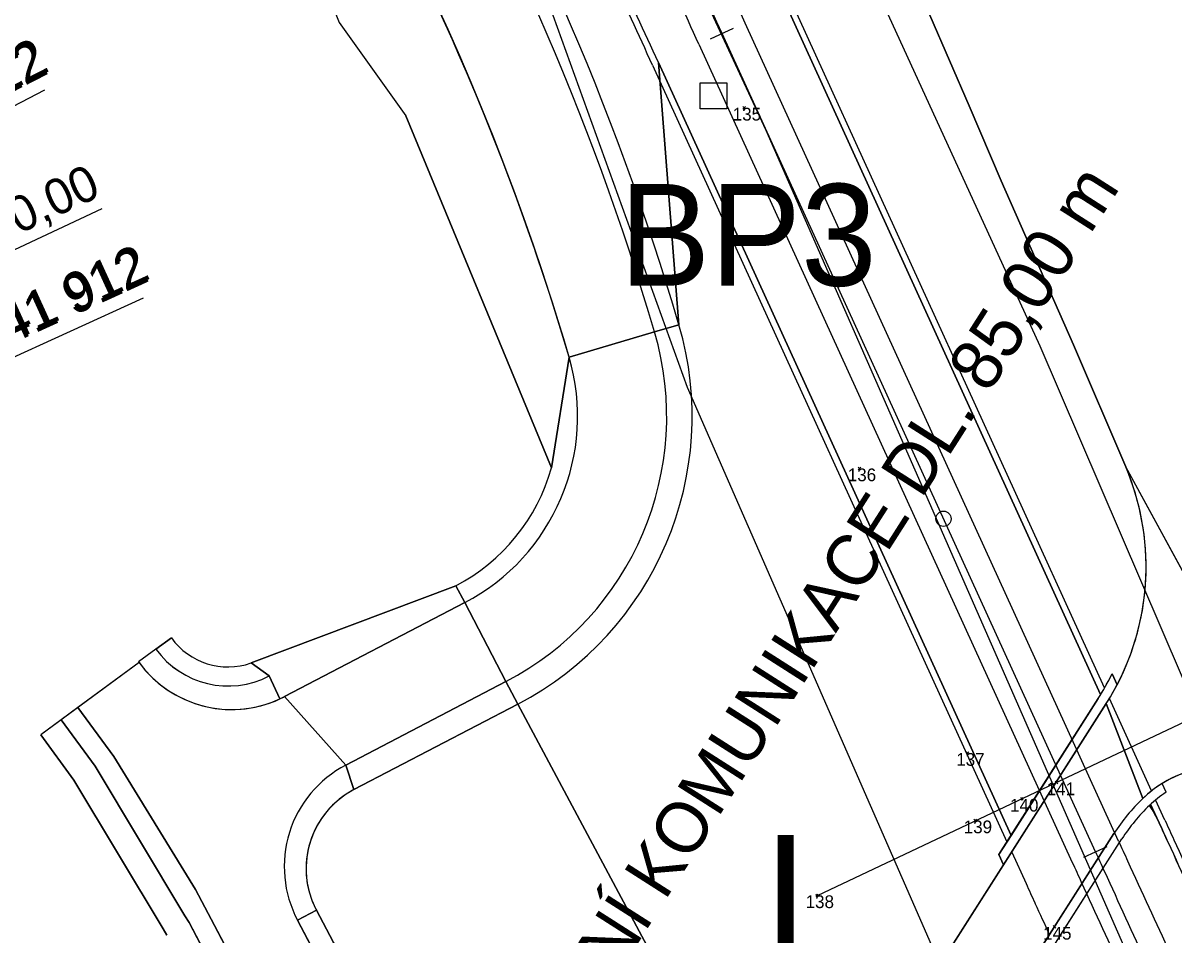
# Model space of a CAD drawing. Extents: x -606444 to -604546, y -1158114 to -1156869.
# Drawn here: x -605195.8 to -605105.4, y -1157332.6 to -1157260.9 of the extents above; entities that cross this region are included whole.
import ezdxf

# ---------------------------------------------------------------- set-up
doc = ezdxf.new("R2010")
doc.units = 0
for name, color, linetype in [('B_CHOD', 7, 'Continuous'), ('B_TRAM', 7, 'Continuous'), ('B_VOZ', 7, 'Continuous'), ('B_ZELEN', 7, 'Continuous'), ('geofyzikální profily_předběžný GTP', 7, 'Continuous'), ('korozní průzkum', 7, 'Continuous'), ('NS_VB', 7, 'Continuous'), ('NS_VB_OBJ', 7, 'Continuous'), ('NS_VB_POP', 7, 'Continuous'), ('OSA', 7, 'Continuous'), ('OSAPOP', 7, 'Continuous'), ('podélný profil trasou tramvaje', 7, 'Continuous'), ('stabilitní profily_předběžný GTP', 7, 'Continuous')]:
    doc.layers.add(name, color=color, linetype=linetype)

msp = doc.modelspace()

# ---------------------------------------------------------------- linework, layer by layer
for p, q in [((-605139.16, -1157267.56), (-605139.26, -1157267.46)), ((-605139.16, -1157267.56), (-605139.26, -1157267.66)), ((-605139.16, -1157267.56), (-605139.06, -1157267.46)), ((-605139.16, -1157267.56), (-605139.06, -1157267.66)), ((-605130.09, -1157295.9), (-605130.19, -1157295.8)), ((-605130.09, -1157295.9), (-605130.19, -1157296)), ((-605130.09, -1157295.9), (-605129.99, -1157295.8)), ((-605130.09, -1157295.9), (-605129.99, -1157296)), ((-605121.59, -1157318.26), (-605121.69, -1157318.16)), ((-605121.59, -1157318.26), (-605121.69, -1157318.36)), ((-605121.59, -1157318.26), (-605121.49, -1157318.16)), ((-605121.59, -1157318.26), (-605121.49, -1157318.36)), ((-605114.6, -1157320.57), (-605114.7, -1157320.47)), ((-605114.6, -1157320.57), (-605114.7, -1157320.67)), ((-605114.6, -1157320.57), (-605114.5, -1157320.47)), ((-605114.6, -1157320.57), (-605114.5, -1157320.67)), ((-605117.32, -1157321.86), (-605117.42, -1157321.76)), ((-605117.32, -1157321.86), (-605117.42, -1157321.96)), ((-605117.32, -1157321.86), (-605117.22, -1157321.76)), ((-605117.32, -1157321.86), (-605117.22, -1157321.96)), ((-605121, -1157323.56), (-605121.1, -1157323.46)), ((-605121, -1157323.56), (-605121.1, -1157323.66)), ((-605121, -1157323.56), (-605120.9, -1157323.46)), ((-605121, -1157323.56), (-605120.9, -1157323.66)), ((-605133.43, -1157329.44), (-605133.53, -1157329.34)), ((-605133.43, -1157329.44), (-605133.53, -1157329.54)), ((-605133.43, -1157329.44), (-605133.33, -1157329.34)), ((-605133.43, -1157329.44), (-605133.33, -1157329.54)), ((-605114.76, -1157331.92), (-605114.86, -1157331.82)), ((-605114.76, -1157331.92), (-605114.86, -1157332.02)), ((-605114.76, -1157331.92), (-605114.66, -1157331.82)), ((-605114.76, -1157331.92), (-605114.66, -1157332.02))]:
    msp.add_line(p, q)
at = {"layer": 'B_CHOD'}
for points in [[(-605144.283, -1157284.607), (-605146.202, -1157285.171)], [(-605146.202, -1157285.171), (-605144.283, -1157284.607)], [(-605185.393, -1157310.096), (-605186.756, -1157311.089)], [(-605109.841, -1157312.897), (-605110.24, -1157312.023)], [(-605175.648, -1157314.004), (-605176.488, -1157312.197)], [(-605170.468, -1157319.208), (-605169.829, -1157321.13), (-605156.956, -1157314.418), (-605157.881, -1157312.645), (-605170.468, -1157319.208)], [(-605157.881, -1157312.645), (-605156.956, -1157314.418)], [(-605179.53, -1157337.76), (-605173.71, -1157348.76), (-605178.07, -1157336.98), (-605182.29, -1157328.99), (-605188.69, -1157318.53), (-605191.523, -1157314.683), (-605192.834, -1157315.649), (-605190.17, -1157319.29), (-605183.11, -1157331.05), (-605182.79, -1157331.58), (-605179.53, -1157337.76)], [(-605111.329, -1157313.973), (-605118.182, -1157324.725), (-605119.142, -1157326.233), (-605118.771, -1157327.046)], [(-605118.771, -1157327.046), (-605110.697, -1157314.376)], [(-605169.829, -1157321.13), (-605170.468, -1157319.208)], [(-605105.987, -1157321.339), (-605106.301, -1157320.651)], [(-605110.093, -1157324.593), (-605115.8, -1157333.547)], [(-605115.427, -1157334.358), (-605109.46, -1157324.996)], [(-605170.68, -1157334.59), (-605172.783, -1157330.604), (-605174.263, -1157331.396), (-605172.24, -1157335.22)], [(-605174.263, -1157331.396), (-605172.783, -1157330.604)]]:
    msp.add_lwpolyline(points, dxfattribs=at)
for centre, radius, start, end in [((-605345.258, -1157343.763), 209.5, 16.40172, 45.63179), ((-605345.258, -1157343.763), 207.5, 16.40172, 45.63179), ((-605168.746, -1157291.807), 25.5, 297.53865, 16.40172), ((-605168.746, -1157291.807), 23.5, 297.53865, 16.40172), ((-605179.724, -1157305.99), 7, 215.91717, 297.53793), ((-605179.443, -1157305.843), 9, 215.65279, 294.93762), ((-605127.563, -1157303.627), 19.25, 327.49041, 334.14232), ((-605127.563, -1157303.627), 20, 327.49041, 332.38659), ((-605166.307, -1157327.188), 9, 117.53922, 207.87635), ((-605166.307, -1157327.188), 9, 117.5386, 117.53916), ((-605101.596, -1157328.323), 9, 121.51853, 133.79374), ((-605166.592, -1157327.337), 7, 117.53865, 207.8197), ((-605097.443, -1157332.654), 15, 133.79385, 147.49041), ((-605101.596, -1157328.323), 8.25, 122.1567, 133.79445), ((-605097.443, -1157332.654), 14.25, 133.79427, 147.49041)]:
    msp.add_arc(centre, radius, start, end, dxfattribs=at)
at = {"layer": 'B_TRAM'}
for p, q in [((-605111.138, -1157313.667), (-605135.892, -1157259.446)), ((-605145.901, -1157264.009), (-605118.182, -1157324.725)), ((-605118.182, -1157324.725), (-605111.329, -1157313.973)), ((-605107.208, -1157322.276), (-605106.542, -1157323.734)), ((-605114.467, -1157332.852), (-605109.46, -1157324.996))]:
    msp.add_line(p, q, dxfattribs=at)
for centre, radius, start, end in [((-606162.126, -1157726.49), 1116.513, 24.470135, 24.878824), ((-605127.563, -1157303.627), 19.25, 327.49041, 328.56341), ((-605097.443, -1157332.654), 14.25, 133.79403, 147.49041), ((-605101.596, -1157328.323), 8.25, 132.86246, 133.79403), ((-494968.988, -1107033.358), 121076.021, 204.54211462, 204.54291835), ((-603789.869, -1156724.367), 1446.674, 204.542918, 204.858777)]:
    msp.add_arc(centre, radius, start, end, dxfattribs=at)
at = {"layer": 'B_VOZ'}
for points in [[(-605146.202, -1157285.171), (-605152.917, -1157287.148)], [(-605152.917, -1157287.148), (-605146.202, -1157285.171)], [(-605094.5, -1157322.63), (-605109.168, -1157295.775)], [(-605161.117, -1157306.438), (-605175.281, -1157313.823), (-605170.468, -1157319.208), (-605157.881, -1157312.645), (-605161.117, -1157306.438)], [(-605161.117, -1157306.438), (-605157.881, -1157312.645)], [(-605186.716, -1157311.143), (-605191.523, -1157314.683), (-605188.69, -1157318.53), (-605182.29, -1157328.99), (-605178.07, -1157336.98), (-605164.08, -1157363.64), (-605161.97, -1157368.95), (-605160.55, -1157374.03)], [(-605170.468, -1157319.208), (-605175.281, -1157313.823)], [(-605107.824, -1157321.827), (-605110.697, -1157314.376), (-605135.867, -1157353.871), (-605140.32, -1157359.56), (-605147.03, -1157366.39), (-605148.32, -1157367.65), (-605149.67, -1157368.45), (-605151.23, -1157368.79), (-605152.44, -1157368.76), (-605153.74, -1157368.34), (-605154.79, -1157367.67), (-605155.63, -1157366.76), (-605162.42, -1157353.9), (-605163.4, -1157352.04), (-605172.24, -1157335.22), (-605174.263, -1157331.396)], [(-605110.697, -1157314.376), (-605107.824, -1157321.827)], [(-605142.56, -1157370.59), (-605135.48, -1157363.22), (-605130.78, -1157357.13), (-605120.39, -1157340.75), (-605110.093, -1157324.593)]]:
    msp.add_lwpolyline(points, dxfattribs=at)
for centre, radius, start, end in [((-605345.258, -1157343.763), 207.5, 16.40172, 45.63179), ((-605345.258, -1157343.763), 200.5, 16.40172, 45.63179), ((-605168.746, -1157291.807), 23.5, 297.53865, 16.40172), ((-605168.746, -1157291.807), 16.5, 297.53865, 16.40172), ((-605127.563, -1157303.627), 20, 327.49041, 23.11654), ((-605179.443, -1157305.843), 9, 216.08051, 297.53822), ((-605166.307, -1157327.188), 9, 117.53865, 207.87635), ((-605101.596, -1157328.323), 9, 30.3498, 133.79403), ((-605097.443, -1157332.654), 15, 133.79403, 147.49041)]:
    msp.add_arc(centre, radius, start, end, dxfattribs=at)
at = {"layer": 'B_ZELEN'}
for p, q in [((-605192.834, -1157315.649), (-605194.445, -1157316.835)), ((-605190.17, -1157319.29), (-605192.834, -1157315.649)), ((-605194.445, -1157316.835), (-605191.838, -1157320.398)), ((-605183.11, -1157331.05), (-605190.17, -1157319.29)), ((-605191.838, -1157320.398), (-605184.823, -1157332.082)), ((-605105.987, -1157321.339), (-605106.301, -1157320.651)), ((-605182.79, -1157331.58), (-605183.11, -1157331.05)), ((-605179.53, -1157337.76), (-605182.79, -1157331.58)), ((-605184.823, -1157332.082), (-605184.532, -1157332.564))]:
    msp.add_line(p, q, dxfattribs=at)
for points in [[(-605182.081, -1157232.827), (-605170.994, -1157260.847), (-605165.739, -1157268.193)], [(-605121.47, -1157267.41), (-605130.49, -1157246.6), (-605135.892, -1157259.446), (-605111.138, -1157313.667)], [(-605156.956, -1157314.418), (-605135.867, -1157353.871), (-605118.771, -1157327.046), (-605119.142, -1157326.233), (-605118.182, -1157324.725), (-605145.901, -1157264.009), (-605144.283, -1157284.607)], [(-605144.283, -1157284.607), (-605145.901, -1157264.009)], [(-605109.168, -1157295.775), (-605113.26, -1157286.19), (-605118.95, -1157273.31), (-605121.47, -1157267.41)], [(-605165.739, -1157268.193), (-605154.3, -1157295.847), (-605152.917, -1157287.148)], [(-605152.917, -1157287.148), (-605154.3, -1157295.847)], [(-605161.811, -1157305.108), (-605177.914, -1157311.183), (-605176.488, -1157312.197), (-605175.648, -1157314.004)], [(-605175.281, -1157313.823), (-605161.117, -1157306.438), (-605161.811, -1157305.108)], [(-605161.811, -1157305.108), (-605161.117, -1157306.438)], [(-605184.179, -1157309.216), (-605185.393, -1157310.096)], [(-605176.488, -1157312.197), (-605177.914, -1157311.183)], [(-605110.24, -1157312.023), (-605109.841, -1157312.897)], [(-605140.32, -1157359.56), (-605135.867, -1157353.871), (-605156.956, -1157314.418), (-605169.829, -1157321.13)], [(-605172.783, -1157330.604), (-605170.68, -1157334.59), (-605162.66, -1157349.9), (-605162.3, -1157349.7), (-605159.13, -1157347.99), (-605157.35, -1157351.33), (-605160.55, -1157353.02), (-605160.95, -1157353.18), (-605153.78, -1157366.59), (-605152.52, -1157367.17), (-605151.083, -1157367.17), (-605149.97, -1157366.92), (-605149.03, -1157366.34), (-605148.31, -1157365.52), (-605147.03, -1157366.39), (-605140.32, -1157359.56)]]:
    msp.add_lwpolyline(points, dxfattribs=at)
for centre, radius, start, end in [((-605345.258, -1157343.763), 209.5, 16.40172, 45.63179), ((-605345.258, -1157343.763), 200.5, 16.40172, 43.57577), ((-606162.126, -1157726.49), 1116.513, 24.470135, 24.878845), ((-605168.746, -1157291.807), 25.5, 297.53865, 16.40172), ((-605168.746, -1157291.807), 16.5, 297.53865, 16.40172), ((-605168.746, -1157291.807), 15, 297.53865, 344.37506), ((-605127.563, -1157303.627), 20, 332.38659, 23.11654), ((-605179.724, -1157305.99), 5.5, 215.91622, 289.21809), ((-605179.724, -1157305.99), 7, 215.91717, 297.53793), ((-605127.563, -1157303.627), 19.25, 328.56341, 334.14232), ((-605179.443, -1157305.843), 9, 295.64103, 297.53865), ((-605179.443, -1157305.843), 9, 294.93762, 295.64103), ((-605101.596, -1157328.323), 9, 30.3498, 121.51853), ((-605166.592, -1157327.337), 7, 117.53865, 206.56505), ((-605101.596, -1157328.323), 8.25, 122.1567, 133.79403), ((-605115.564, -1157327.879), 9.928, 24.67293, 33.71295), ((-605445.452, -1157479.422), 372.959, 24.4121, 24.67293), ((-604385.242, -1156998.219), 791.343, 204.412101, 204.989572), ((-605166.592, -1157327.337), 7, 206.56505, 207.8197)]:
    msp.add_arc(centre, radius, start, end, dxfattribs=at)
at = {"layer": 'geofyzikální profily_předběžný GTP'}
for points in [[(-605670.777, -1157141.05), (-605656.017, -1157139.471), (-605613.877, -1157139.359), (-605584.802, -1157137.32), (-605531.406, -1157136.329), (-605491.561, -1157133.405), (-605482.073, -1157135.613), (-605438.781, -1157126.664), (-605383.232, -1157124.522), (-605352.341, -1157123.33), (-605321.946, -1157125.999), (-605284.139, -1157130.42), (-605243.303, -1157142.595), (-605207.83, -1157158.833), (-605179.979, -1157186.151), (-605165.292, -1157202.666), (-605149.231, -1157223.341), (-605135.067, -1157244.471), (-605115.915, -1157286.275), (-605103.218, -1157315.843), (-605095.331, -1157330.321), (-605036.966, -1157403.361), (-604999.079, -1157442.536), (-604970.798, -1157468.352)], [(-605668.887, -1157175.563), (-605638.047, -1157172.713), (-605616.091, -1157172.842), (-605512.92, -1157173.16), (-605468.488, -1157175.648), (-605413.499, -1157174.062), (-605313.444, -1157169.44), (-605274.571, -1157178.007), (-605221.389, -1157204.274), (-605178.573, -1157224.003), (-605160.32, -1157243.281), (-605143.644, -1157289.502), (-605117.165, -1157349.927), (-605096.208, -1157389.159), (-605065.898, -1157426.812), (-605053.52, -1157443.58), (-605045.82, -1157465.15), (-605020.205, -1157502.195)]]:
    msp.add_lwpolyline(points, dxfattribs=at)
at = {"layer": 'korozní průzkum'}
msp.add_lwpolyline([(-605142.61, -1157265.604), (-605140.529, -1157265.604), (-605140.529, -1157267.641), (-605142.61, -1157267.641)], close=True, dxfattribs=at)
at = {"layer": 'NS_VB'}
for p, q in [((-605130.49, -1157246.6), (-605121.47, -1157267.41)), ((-605170.994, -1157260.847), (-605165.739, -1157268.193)), ((-605121.47, -1157267.41), (-605118.95, -1157273.31)), ((-605154.3, -1157295.847), (-605165.739, -1157268.193)), ((-605118.95, -1157273.31), (-605113.26, -1157286.19)), ((-605113.26, -1157286.19), (-605109.168, -1157295.775)), ((-605094.5, -1157322.63), (-605109.168, -1157295.775)), ((-605177.914, -1157311.183), (-605161.811, -1157305.108)), ((-605175.281, -1157313.823), (-605161.117, -1157306.438)), ((-605185.393, -1157310.096), (-605184.179, -1157309.216)), ((-605185.393, -1157310.096), (-605186.756, -1157311.089)), ((-605186.756, -1157311.089), (-605186.716, -1157311.143)), ((-605186.716, -1157311.143), (-605194.445, -1157316.835)), ((-605176.488, -1157312.197), (-605175.648, -1157314.004)), ((-605170.468, -1157319.208), (-605157.881, -1157312.645)), ((-605191.523, -1157314.683), (-605188.69, -1157318.53)), ((-605169.829, -1157321.13), (-605156.956, -1157314.418)), ((-605135.867, -1157353.871), (-605110.697, -1157314.376)), ((-605119.142, -1157326.233), (-605111.329, -1157313.973)), ((-605190.17, -1157319.29), (-605192.834, -1157315.649)), ((-605191.838, -1157320.398), (-605194.445, -1157316.835)), ((-605188.69, -1157318.53), (-605182.29, -1157328.99)), ((-605183.11, -1157331.05), (-605190.17, -1157319.29)), ((-605184.823, -1157332.082), (-605191.838, -1157320.398)), ((-605120.39, -1157340.75), (-605110.093, -1157324.593)), ((-605115.427, -1157334.358), (-605109.46, -1157324.996)), ((-605182.29, -1157328.99), (-605178.07, -1157336.98)), ((-605172.778, -1157330.613), (-605172.783, -1157330.604)), ((-605172.778, -1157330.613), (-605170.68, -1157334.59)), ((-605182.79, -1157331.58), (-605183.11, -1157331.05)), ((-605179.53, -1157337.76), (-605182.79, -1157331.58)), ((-605172.24, -1157335.22), (-605174.263, -1157331.396)), ((-605184.532, -1157332.564), (-605184.823, -1157332.082))]:
    msp.add_line(p, q, dxfattribs=at)
for points in [[(-605111.138, -1157313.667), (-605135.892, -1157259.446)], [(-605145.901, -1157264.009), (-605118.182, -1157324.725)], [(-605109.841, -1157312.897), (-605110.24, -1157312.023)], [(-605105.987, -1157321.339), (-605106.301, -1157320.651)], [(-605106.542, -1157323.735), (-605107.208, -1157322.276)], [(-605119.142, -1157326.233), (-605118.771, -1157327.046)]]:
    msp.add_lwpolyline(points, dxfattribs=at)
for centre, radius, start, end in [((-605345.258, -1157343.763), 200.5, 16.40172, 97.57988), ((-605345.258, -1157343.763), 209.5, 16.40172, 45.63179), ((-605345.258, -1157343.763), 207.5, 16.40172, 45.63179), ((-606162.126, -1157726.49), 1116.513, 24.470135, 24.878824), ((-605168.746, -1157291.807), 25.5, 297.53865, 16.40172), ((-605168.746, -1157291.807), 23.5, 297.53865, 16.40172), ((-605168.746, -1157291.807), 16.5, 297.53865, 16.40172), ((-605168.746, -1157291.807), 15, 297.53865, 344.37506), ((-605127.563, -1157303.627), 20, 327.49041, 23.11654), ((-605179.724, -1157305.99), 5.5, 215.91622, 289.21846), ((-605179.724, -1157305.99), 7, 215.91622, 297.53865), ((-605179.443, -1157305.843), 9, 216.08016, 297.53865), ((-605127.563, -1157303.627), 19.25, 327.49041, 334.14232), ((-605166.307, -1157327.188), 9, 117.53865, 207.87635), ((-605101.596, -1157328.323), 9, 30.3498, 133.79403), ((-605166.592, -1157327.337), 7, 117.53865, 207.8197), ((-605097.443, -1157332.654), 15, 133.79403, 147.49041), ((-605101.596, -1157328.323), 8.25, 122.1567, 133.79403), ((-605097.443, -1157332.654), 14.25, 133.79403, 147.49041), ((-597970.958, -1154066.398), 7843.902, 204.5363189, 204.5487439), ((-604045.754, -1156842.066), 1165.02, 204.504893, 204.896591)]:
    msp.add_arc(centre, radius, start, end, dxfattribs=at)
at = {"layer": 'NS_VB_OBJ'}
for points in [[(-605110.828, -1157313.142), (-605135.437, -1157259.239)], [(-605146.356, -1157264.216), (-605118.502, -1157325.228)], [(-605107.136, -1157321.23), (-605110.448, -1157313.975)], [(-605106.087, -1157323.527), (-605106.814, -1157321.934)], [(-605118.131, -1157326.041), (-605117.003, -1157328.511)]]:
    msp.add_lwpolyline(points, dxfattribs=at)
for centre, radius, start, end in [((-606162.126, -1157726.49), 1116.013, 24.47012, 24.878824), ((-597970.948, -1154066.393), 7843.413, 204.5363188, 204.5487453), ((-604045.754, -1156842.066), 1164.52, 204.504884, 204.896591), ((-597970.959, -1154066.398), 7855.401, 204.5363204, 204.5487119), ((-604045.754, -1156842.066), 1176.52, 204.505108, 204.638321)]:
    msp.add_arc(centre, radius, start, end, dxfattribs=at)
at = {"layer": 'OSA'}
msp.add_line((-605111.545, -1157326.019), (-605140.896, -1157261.728), dxfattribs=at)
for points in [[(-605109.726, -1157325.188), (-605139.077, -1157260.898)], [(-605142.716, -1157262.557), (-605113.364, -1157326.849)]]:
    msp.add_lwpolyline(points, dxfattribs=at)
for centre, radius, start, end in [((-606162.126, -1157726.49), 1124.013, 24.470364, 24.878824), ((-606162.126, -1157726.49), 1122.013, 24.470303, 24.878824), ((-606162.126, -1157726.49), 1120.013, 24.470242, 24.878824), ((-597970.959, -1154066.398), 7847.401, 204.5363194, 204.5487341), ((-597970.958, -1154066.398), 7849.402, 204.5363196, 204.5487286), ((-597970.955, -1154066.397), 7851.405, 204.5363199, 204.548723), ((-604045.754, -1156842.066), 1168.52, 204.504959, 204.896591), ((-604045.754, -1156842.066), 1170.52, 204.504996, 204.896591), ((-604045.754, -1156842.066), 1172.52, 204.505033, 204.896591)]:
    msp.add_arc(centre, radius, start, end, dxfattribs=at)
at = {"layer": 'OSAPOP'}
for p, q in [((-605141.806, -1157262.143), (-605139.987, -1157261.312)), ((-605216.363, -1157277.581), (-605194.126, -1157266.156)), ((-605198.671, -1157279.693), (-605189.605, -1157275.474)), ((-605209.123, -1157292.875), (-605186.381, -1157282.493)), ((-605112.455, -1157326.434), (-605110.635, -1157325.604))]:
    msp.add_line(p, q, dxfattribs=at)
msp.add_circle((-605123.49, -1157299.854), 0.6, dxfattribs=at)
at = {"layer": 'podélný profil trasou tramvaje'}
msp.add_lwpolyline([(-605085.67, -1157373.96), (-605102.483, -1157348.991), (-605137.415, -1157269.352), (-605142.94, -1157257.48), (-605148.09, -1157246.14), (-605156.56, -1157230.62), (-605167.27, -1157214.45), (-605176.96, -1157202.08), (-605190.28, -1157187.63), (-605201.93, -1157176.87), (-605210.19, -1157170.251), (-605214.51, -1157166.83), (-605234.53, -1157153.68), (-605243.13, -1157148.91), (-605255.42, -1157142.97), (-605270.4, -1157136.88), (-605273.539, -1157135.893), (-605289.22, -1157131.03), (-605304.97, -1157127.5), (-605318.55, -1157125.25), (-605341.868, -1157123.876), (-605358.234, -1157124.224), (-605590.305, -1157143.817)], dxfattribs=at)
at = {"layer": 'stabilitní profily_předběžný GTP'}
msp.add_lwpolyline([(-605133.4, -1157329.44), (-605089.73, -1157308.8)], dxfattribs=at)

# ---------------------------------------------------------------- texts
for s, p in [('135', (-605140.058, -1157268.56)), ('136', (-605131.015, -1157296.9)), ('137', (-605122.488, -1157319.26)), ('141', (-605115.379, -1157321.57)), ('140', (-605118.261, -1157322.86)), ('139', (-605121.902, -1157324.56)), ('138', (-605134.328, -1157330.44)), ('145', (-605115.658, -1157332.92))]:
    msp.add_text(s, height=1).set_placement(p)
at = {"layer": 'korozní průzkum'}
msp.add_text('BP3', height=8, dxfattribs=at).set_placement((-605148.959, -1157281.541))
at = {"layer": 'NS_VB_POP'}
msp.add_text('MÍSTNÍ KOMUNIKACE DL. 85,00 m', height=4, rotation=57.44727, dxfattribs=at).set_placement((-605155.944, -1157346.456))
at = {"layer": 'OSAPOP'}
for s, height, rotation, p in [('PK  0,362 312', 3, 27.19483, (-605216.266, -1157276.239)), ('PK  0,362 312', 3, 27.19483, (-605216.331, -1157276.44)), ('50,00', 2.8, 24.95603, (-605198.086, -1157278.391)), ('TP  0,341 912', 3, 24.53839, (-605208.645, -1157291.393)), ('TP  0,341 912', 3, 24.53839, (-605208.719, -1157291.592))]:
    msp.add_text(s, height=height, rotation=rotation, dxfattribs=at).set_placement(p)
at = {"layer": 'stabilitní profily_předběžný GTP'}
msp.add_text('I', height=10, dxfattribs=at).set_placement((-605137.749, -1157334.707))

doc.saveas('drawing.dxf')
